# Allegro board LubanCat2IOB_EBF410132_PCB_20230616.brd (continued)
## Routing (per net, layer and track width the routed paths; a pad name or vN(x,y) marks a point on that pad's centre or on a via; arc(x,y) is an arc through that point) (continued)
UART4_RX_M1: length 79.3
  TOP w0.156: J4.17 v1(61.28,64.94)
  ART04 w0.142: v1(61.28,64.94) 61.28,32.76 v1(59,30.48)
  BOTTOM w0.156: v1(59,30.48) 58.52,30.96 58.52,32.07 58.83,32.38 60.43,32.38 60.8,32.01 60.8,27.72 60.41,27.33 59.61,27.33 55.68,23.39 54.08,23.39 53.47,24 51.79,24 51.38,24.41 40.61,24.41 40.28,24.08 40.28,21.44 40.13,21.28 39.01,21.28 38.61,20.88 38.61,17.78 37.62,16.79 U13.1
UART4_TX_M1: length 76.4
  TOP w0.156: J4.15 60.78,65.44 v1(60.28,65.94)
  ART04 w0.142: v1(60.28,65.94) 60.78,65.44 60.78,33.25 v1(59,31.48)
  BOTTOM w0.156: v1(59,31.48) 59.61,30.87 59.61,27.94 56.08,24.41 52.01,24.41 51.04,25.38 33.66,25.38 33.22,24.94 33.22,21.95 34.57,20.6 U13.4
UART7_RX: length 21.7
  TOP w0.156: R50.2 92.56,22.3 92.56,19.68 D9.1 91.82,16.89 91.57,16.63 87.64,16.63 87.33,16.32 87.33,8.25 J13.3
UART7_RX_M1: length 76.1
  TOP w0.156: R50.1 v1(91.82,24.78) ; J4.21 v1(62.28,64.94)
  ART03 w0.142: v1(91.82,24.78) 91.82,28.67 91.49,29 77.19,29 75.54,27.35 69.16,27.35 66.1,30.41 64.02,30.41 63.75,30.15 63.75,29.42 v1(64.28,28.89)
  ART04 w0.142: v1(64.28,28.89) 64.85,29.45 64.85,31.26 64.56,31.54 63.1,31.54 62.81,31.83 62.81,38.69 62.28,39.22 v1(62.28,64.94)
UART7_TX: length 17.6
  TOP w0.156: J13.4 86.99,10.45 86.99,16.63 87.3,16.94 89.91,16.94 90.22,17.25 D8.1 90.92,19.63 90.92,22.35 R49.2
UART7_TX_M1: length 73.3
  TOP w0.156: J4.19 61.78,65.44 v1(61.28,65.94) ; R49.1 v1(90.22,24.78)
  ART03 w0.142: v1(90.22,24.78) 90.2,24.8 90.2,28.41 89.91,28.7 77.44,28.7 75.72,26.97 69.01,26.97 66.09,29.89 v1(64.28,29.89)
  ART04 w0.142: v1(61.28,65.94) 61.8,65.43 61.8,39.02 62.41,38.41 62.41,30.18 62.69,29.89 v1(64.28,29.89)
UART9_RX: length 13
  TOP w0.156: R44.2 87.65,22.41 87.65,19.57 D7.1 87.02,17.99 86.71,17.67 85.18,17.67 84.87,17.36 84.87,13.73 J14.3
UART9_RX_M1: length 77.3
  TOP w0.156: J4.5 v1(58.28,64.94) ; R44.1 v1(87.02,24.78)
  ART03 w0.142: v1(55,30.48) 55.49,29.99 62.72,29.99 63.01,29.71 63.01,27.66 63.29,27.38 67.64,27.38 68.78,26.23 78.87,26.23 80.98,28.34 86.74,28.34 87.02,28.06 v1(87.02,24.78)
  ART04 w0.142: v1(58.28,64.94) 58.28,62.83 55.91,60.45 55.91,34.06 55,33.16 v1(55,30.48)
UART9_TX: length 10.7
  TOP w0.156: R43.2 89.25,22.41 89.25,19.57 D6.1 88.62,17.63 88.31,17.32 86.13,17.32 85.85,17.04 85.85,15.29
UART9_TX_M1: length 83.2
  TOP w0.156: R43.1 v1(88.62,24.78) ; J4.3 57.78,65.44 v1(57.28,65.94)
  ART03 w0.142: v1(88.62,24.78) 88.62,24.44 88.34,24.15 86.82,24.15 86.44,24.53 86.44,27.68 86.15,27.96 81.1,27.96 78.97,25.83 68.66,25.83 67.44,27.05 62.92,27.05 62.64,27.33 62.64,29.4 62.35,29.69 54.79,29.69 v1(54,30.48)
  ART04 w0.142: v1(54,30.48) 54.51,30.98 54.51,33.32 55.58,34.39 55.58,60.7 57.76,62.89 57.76,65.46 v1(57.28,65.94)
USB2_HOST2_DM: length 104.7
  TOP w0.158: v1(115.93,65.8) 115.63,65.51 99.17,65.51 98.48,64.82 88.7,64.82 87.17,63.29 87.17,58.14 86.41,57.38 75.56,57.38 75.21,57.73 75.21,58.12 75.28,58.19 J4.74 ; R152.2 v1(127.28,78.58)
  ART04 w0.144: v1(127.28,78.58) 126.94,78.25 126.94,77.54 126.48,77.07 122.24,77.07 121.57,76.4 102.21,76.4 101.65,75.84 101.65,63.6 101.88,63.37 111.71,63.37 113.84,65.5 115.62,65.5 v1(115.93,65.8)
USB2_HOST2_DP: length 105.9
  TOP w0.158: J4.72 74.78,58.19 74.85,58.12 74.85,57.58 75.41,57.02 86.56,57.02 87.53,57.99 87.53,63.14 88.85,64.46 98.63,64.46 99.32,65.15 115.62,65.15 v1(115.93,64.84) ; R153.2 v1(126.26,78.58)
  ART04 w0.144: v1(126.26,78.58) 126.6,78.25 126.6,77.68 126.33,77.42 122.1,77.42 121.43,76.75 102.07,76.75 101.3,75.98 101.3,63.45 101.74,63.02 111.85,63.02 113.98,65.15 115.62,65.15 v1(115.93,64.84)
USB2_HOST3_DM: length 74.1
  TOP w0.158: v1(89.13,62.86) 89.43,62.56 89.43,57.7 87.59,55.86 74.62,55.86 73.71,56.76 73.71,58.12 73.78,58.19 J4.68
  BOTTOM w0.158: v1(89.13,62.86) 89.43,62.56 89.43,62.02 89.79,61.66 96.39,61.66 98.75,64.02 98.75,94.12 99.09,94.46 99.47,94.46 arc(99.57,94.42) 99.62,94.31 arc(99.66,94.2) 99.77,94.15 100.1,94.15 arc(100.21,94.2) 100.25,94.31 arc(100.3,94.42) 100.41,94.46 100.73,94.46 arc(100.84,94.42) 100.89,94.31 arc(100.93,94.2) 101.04,94.15 101.36,94.15 arc(101.47,94.2) 101.52,94.31 arc(101.56,94.42) 101.67,94.46 104.78,94.46 104.85,94.39 U28.14
USB2_HOST3_DP: length 74
  TOP w0.158: v1(90.1,62.86) 89.79,62.56 89.79,57.56 87.73,55.5 74.47,55.5 73.35,56.61 73.35,58.12 73.28,58.19 J4.66
  BOTTOM w0.158: v1(90.1,62.86) 89.79,62.56 89.79,62.17 89.94,62.02 96.24,62.02 98.39,64.17 98.39,94.27 98.94,94.82 104.78,94.82 104.85,94.89 U28.15
USB3_HOST1_DM: length 157.6
  TOP w0.158: v1(115.73,37.04) 116,37.31 116,38.52 115.68,38.84 53.63,38.84 51.71,36.92 51.71,27.76 51.78,27.69 J1.80 ; R148.2 v1(121.06,78.58)
  ART04 w0.144: v1(121.06,78.58) 120.46,77.99 100.96,77.99 100.06,77.09 100.06,53.71 100.75,53.01 103.9,53.01 arc(103.97,52.99) 104,52.92 arc(104.02,52.86) 104.09,52.83 104.48,52.83 arc(104.54,52.86) 104.57,52.92 arc(104.6,52.99) 104.66,53.01 105.05,53.01 arc(105.12,52.99) 105.15,52.92 arc(105.17,52.86) 105.24,52.83 105.63,52.83 arc(105.69,52.86) 105.72,52.92 arc(105.75,52.99) 105.81,53.01 117.07,53.01 117.36,52.73 117.36,40.32 116.04,39 116.04,37.35 v1(115.73,37.04)
USB3_HOST1_DP: length 159
  TOP w0.158: v1(116.69,37.04) 116.36,37.37 116.36,38.67 115.83,39.2 53.48,39.2 51.35,37.07 51.35,27.76 51.28,27.69 J1.78 ; R149.2 v1(122.07,78.58)
  ART04 w0.144: v1(122.07,78.58) 122.05,78.56 121.71,78.56 121.25,78.11 121.07,78.11 120.61,77.64 101.1,77.64 100.41,76.95 100.41,53.85 100.9,53.36 117.21,53.36 117.7,52.87 117.7,40.18 116.38,38.86 116.38,37.35 v1(116.69,37.04)
USB3_HOST1_SSRXN: length 158.4
  TOP w0.158: R150.2 v1(123.09,78.58) ; v1(113.36,45.36) 113.06,45.06 113.06,43.85 112.69,43.48 50.53,43.48 46.71,39.67 46.71,27.76 46.78,27.69 J1.60
  ART04 w0.144: v1(113.36,45.36) 113.05,45.67 113.05,51.84 112.7,52.18 99.6,52.18 99.15,52.63 99.15,80.35 99.75,80.95 118.35,80.95 119.54,79.76 123.09,79.76 123.42,79.43 123.42,78.92 v1(123.09,78.58)
USB3_HOST1_SSRXP: length 159.6
  TOP w0.158: R151.2 v1(124.1,78.58) ; J1.58 46.28,27.69 46.35,27.76 46.35,39.82 50.38,43.85 112.54,43.85 112.69,44 112.69,45.06 v1(112.39,45.36)
  ART04 w0.144: v1(112.39,45.36) 112.7,45.67 112.7,51.69 112.56,51.84 99.46,51.84 98.81,52.49 98.81,80.5 99.61,81.3 118.49,81.3 119.68,80.11 123.24,80.11 123.77,79.57 123.77,78.92 v1(124.1,78.58)
USB3_HOST1_SSTXN: length 186.5
  TOP w0.158: J1.64 47.78,27.69 47.71,27.76 47.71,39.28 51.03,42.59 115.48,42.59 116.01,43.12 116.01,45.06 v1(116.31,45.36) ; C142.2 v1(128.3,78.58)
  ART04 w0.144: v1(116.31,45.36) 116,45.05 116,44.24 114.72,42.96 98.07,42.96 97.42,43.61 97.42,80.96 98.7,82.24 115.03,82.24 116.32,83.53 120.06,83.53 120.86,82.72 129.84,82.72 130.45,82.12 130.45,77.56 130.02,77.14 128.98,77.14 128.63,77.48 128.63,78.25 v1(128.3,78.58)
USB3_HOST1_SSTXP: length 186.5
  TOP w0.158: v1(115.34,45.36) 115.65,45.06 115.65,43.27 115.33,42.95 50.88,42.95 47.35,39.43 47.35,27.76 47.28,27.69 J1.62 ; C143.2 v1(129.31,78.58)
  ART04 w0.144: v1(129.31,78.58) 128.98,78.25 128.98,77.63 129.12,77.48 129.88,77.48 130.1,77.7 130.1,79.08 arc(130.04,79.23) 129.9,79.29 arc(129.75,79.35) 129.69,79.49 129.69,79.66 arc(129.75,79.8) 129.9,79.86 arc(130.04,79.92) 130.1,80.06 130.1,80.23 arc(130.04,80.38) 129.9,80.44 arc(129.75,80.5) 129.69,80.64 129.69,80.81 arc(129.75,80.95) 129.9,81.01 arc(130.04,81.07) 130.1,81.21 130.1,81.98 129.7,82.38 120.72,82.38 119.91,83.18 116.46,83.18 115.17,81.89 98.84,81.89 97.76,80.82 97.76,71.08 arc(97.8,70.99) 97.89,70.95 arc(97.98,70.91) 98.02,70.82 98.02,70.5 arc(97.98,70.41) 97.89,70.37 arc(97.8,70.34) 97.76,70.25 97.76,69.93 arc(97.8,69.84) 97.89,69.8 arc(97.98,69.76) 98.02,69.67 98.02,69.35 arc(97.98,69.26) 97.89,69.22 arc(97.8,69.19) 97.76,69.1 97.76,68.78 arc(97.8,68.69) 97.89,68.65 arc(97.98,68.61) 98.02,68.52 98.02,68.2 arc(97.98,68.11) 97.89,68.07 arc(97.8,68.04) 97.76,67.95 97.76,67.63 arc(97.8,67.54) 97.89,67.5 arc(97.98,67.46) 98.02,67.37 98.02,67.05 arc(97.98,66.96) 97.89,66.92 arc(97.8,66.89) 97.76,66.8 97.76,66.51 arc(97.81,66.41) 97.9,66.37 arc(98,66.33) 98.04,66.23 98.04,65.93 arc(98,65.84) 97.9,65.79 arc(97.81,65.75) 97.76,65.66 97.76,65.36 arc(97.81,65.26) 97.9,65.22 arc(98,65.18) 98.04,65.08 98.04,64.78 arc(98,64.69) 97.9,64.64 arc(97.81,64.6) 97.76,64.51 97.76,64.21 arc(97.81,64.11) 97.9,64.07 arc(98,64.03) 98.04,63.93 98.04,63.63 arc(98,63.54) 97.9,63.49 arc(97.81,63.45) 97.76,63.36 97.76,43.75 98.21,43.3 113.4,43.3 arc(113.51,43.35) 113.56,43.47 arc(113.61,43.59) 113.73,43.63 113.97,43.63 arc(114.09,43.59) 114.14,43.47 arc(114.18,43.35) 114.3,43.3 114.57,43.3 115.65,44.39 115.65,45.05 v1(115.34,45.36)
USB3_OTG0_DM: length 107.4
  TOP w0.158: v1(24.55,94.52) J36.B7 24.55,91.78 24.48,91.71 24.48,91.11 25.63,89.96 27.28,89.96 27.44,90.12 ; J36.A7 v1(23.55,94.52) ; v1(40.56,72.59) 40.26,72.89 40.26,80.39 39.45,81.2 30.94,81.2 30.33,81.81 30.33,89.4 29.78,89.95 27.6,89.95 27.44,90.11 27.44,90.12 ; 27.44,90.12 D26.1 ; v1(52.83,29.48) 53.13,29.17 57.84,29.17 58.21,28.8 58.21,27.76 58.28,27.69 J2.6
  BOTTOM w0.158: v1(23.55,94.52) v1(24.55,94.52) ; v1(52.83,29.48) 52.52,29.17 51.34,29.17 51.05,29.46 51.05,30.86 arc(51.11,31) 51.26,31.06 arc(51.4,31.12) 51.46,31.27 51.46,31.49 arc(51.4,31.64) 51.26,31.7 arc(51.11,31.76) 51.05,31.9 51.05,32.13 arc(51.11,32.27) 51.26,32.33 arc(51.4,32.39) 51.46,32.53 51.46,32.76 arc(51.4,32.9) 51.26,32.96 arc(51.11,33.02) 51.05,33.17 51.05,34.21 50.32,34.95 38.43,34.95 38.18,35.2 38.18,59.13 37.19,60.12 37.19,62.28 40.26,65.35 40.26,72.29 v1(40.56,72.59)
USB3_OTG0_DP: length 107.3
  TOP w0.158: 27.44,89.43 27.44,89.44 27.28,89.6 25.48,89.6 24.12,90.96 24.12,91.71 24.05,91.78 J36.A6 24.05,94.88 23.89,95.04 23.21,95.04 23.05,94.88 J36.B6 ; 27.44,89.43 D25.1 ; 27.44,89.43 27.6,89.59 29.63,89.59 29.97,89.25 29.97,81.66 30.79,80.84 39.3,80.84 39.9,80.24 39.9,72.89 v1(39.6,72.59) ; v1(52.83,28.51) 53.13,28.81 57.7,28.81 57.85,28.65 57.85,27.76 57.83,27.73 57.83,27.67 57.78,27.62 J2.4
  BOTTOM w0.158: v1(39.6,72.59) 39.9,72.29 39.9,65.5 36.83,62.43 36.83,59.97 37.82,58.98 37.82,35.05 38.28,34.59 50.17,34.59 50.69,34.06 50.69,29.31 51.19,28.81 52.52,28.81 v1(52.83,28.51)
USB3_OTG0_ID: length 163.2
  TOP w0.156: J2.10 59.28,28.39 v1(58.78,28.89)
  ART03 w0.142: v1(58.78,28.89) 59.5,28.18 59.5,26.74 58.17,25.41 58.17,19.72 57.64,19.19 36.81,19.19 36.53,19.47 36.53,34.16 33.63,37.05 8.53,37.05 8.24,37.34 8.24,72.81 7.06,73.99 7.06,86.89 7.49,87.32 20.07,87.32 21.32,88.58 23.85,88.58 24.13,88.86 24.13,92.27 24.33,92.48 28.69,92.48 v1(28.97,92.76)
  BOTTOM w0.156: R160.2 26.05,96.92 28.91,96.92 29.29,96.54 29.29,93.07 v1(28.97,92.76)
USB3_OTG0_VBUSDET: length 151.7
  TOP w0.156: R158.2 v1(23.61,89.12) ; v1(60.28,28.89) 59.78,28.39 J2.12
  ART03 w0.142: v1(23.61,89.12) 23.1,89.63 21.21,89.63 19.43,87.85 6.53,87.85 6.05,87.37 6.05,73.48 7.81,71.71 7.81,36.83 8.1,36.55 33.5,36.55 35.53,34.52 35.53,19.2 35.84,18.89 57.76,18.89 58.47,19.6 58.47,25.29 59.79,26.62 59.79,28.4 v1(60.28,28.89)
  BOTTOM w0.156: R158.2 v1(23.61,89.12)
USB20_DM1: length 9
  TOP w0.158: R152.1 127.31,80.39 U22.7 U22.4 127.31,83.18 126.55,83.95 126.55,84.58 126.76,84.79 127.17,84.79 127.35,84.97 127.35,86.26 127.18,86.43 126.7,86.43 126.54,86.59 126.54,87.02 126.7,87.18 J19.11
USB20_DP1: length 7.9
  TOP w0.158: R153.1 126.81,80.9 U22.6 U22.5 126.81,83.17 126.19,83.8 126.19,84.58 125.96,84.81 125.55,84.81 125.35,85.01 J19.12
USB20_HOST2_PWR_EN: length 181.1
  TOP w0.156: v1(45.05,10.26) 44.73,10.58 44.73,19.27 43.28,20.72 J1.45
  BOTTOM w0.156: R154.1 117.88,97.99 117.51,97.62 117.51,82.34 117.49,82.32 117.49,78.19 117.8,77.87 120.55,77.87 121.13,77.29 121.13,71.4 120.82,71.09 117.73,71.09 116.51,69.87 116.51,67.94 115.93,67.36 107.96,67.36 107.42,66.82 107.42,57.79 106.45,56.82 106.45,55.29 108.2,53.54 108.2,38.13 107.89,37.82 97.44,37.82 97.05,37.43 97.05,11.76 96.54,11.25 76.68,11.25 74.83,9.39 45.91,9.39 v1(45.05,10.26)
USB20_HUB_PWR_EN: length 107.6
  TOP w0.156: v1(120.02,81.03) 120.04,81.02 R170.1 ; v1(108.31,55.8) 107.83,56.28 96.62,56.28 93.93,53.59 47.6,53.59 47.28,53.9 J3.62
  BOTTOM w0.156: v1(120.02,81.03) 121.27,81.03 121.59,80.72 121.59,71 121.27,70.68 117.93,70.68 116.89,69.64 116.89,67.41 115.85,66.36 108.3,66.36 107.83,65.89 107.83,56.28 v1(108.31,55.8)
USB30_DM: length 25.8
  TOP w0.158: J19.2 126.74,90.38 126.58,90.54 126.58,91.3 126.01,91.87 122.35,91.87 120.44,89.96 117.73,89.96 116.97,89.2 116.97,84.32 117.58,83.71 121.41,83.71 121.62,83.5 121.62,83.16 121.56,83.09 U23.5 U23.6 121.56,80.85 R148.1
USB30_DP: length 24.5
  TOP w0.158: R149.1 122.05,80.37 U23.7 U23.4 122.05,83.09 121.99,83.16 121.99,83.65 121.56,84.07 117.73,84.07 117.33,84.47 117.33,89.05 117.88,89.6 120.59,89.6 122.5,91.51 125.86,91.51 126.22,91.15 126.22,90.55 126.05,90.38 J19.3
USB30_HOST1_PWR_EN: length 188.7
  TOP w0.156: J1.47 43.78,20.78 45.14,19.43 45.14,11.15 45.16,11.15 v1(46.05,10.26)
  BOTTOM w0.156: v1(46.05,10.26) 46.48,9.83 74.32,9.83 76.17,11.68 94.79,11.68 95.35,12.24 95.35,23.39 96.41,24.44 96.41,37.83 96.95,38.38 107.56,38.38 107.87,38.69 107.87,53.34 106.12,55.09 106.12,57.15 106.96,57.98 106.96,67.2 107.59,67.84 115.6,67.84 116.15,68.4 116.15,70.23 117.45,71.52 120.34,71.52 120.65,71.84 120.65,76.98 120.34,77.29 116.8,77.29 116.49,77.6 116.49,83.93 117.14,84.58 117.14,97.71 118.54,99.11 126.85,99.11 R156.1
USB30_RXN: length 11.4
  TOP w0.158: J19.5 121.72,88.88 121.56,88.72 121.56,88.36 121.82,88.11 123.26,88.11 123.9,87.48 123.9,86.99 123.13,86.22 123.13,83.16 123.06,83.09 U23.2 U23.9 123.06,80.39 R150.1
USB30_RXP: length 10.1
  TOP w0.158: R151.1 123.55,80.9 U23.10 U23.1 123.55,83.09 123.49,83.15 123.49,86.07 124.26,86.84 124.26,87.63 123.53,88.36 123.53,88.72 123.69,88.88 J19.6
USB30_TXN: length 10.2
  TOP w0.158: J19.8 129.05,88.88 129.21,88.72 129.21,88.37 128.54,87.7 128.54,86.59 129.13,86 129.13,84.65 128.38,83.91 128.38,83.16 128.31,83.09 U22.2 U22.9 128.31,80.37 C142.1
USB30_TXP: length 10.3
  TOP w0.158: C143.1 128.81,80.85 U22.10 U22.1 128.81,83.09 128.74,83.16 128.74,83.76 129.49,84.5 129.49,86.15 128.91,86.74 128.91,87.55 129.57,88.22 129.57,88.7 129.75,88.88 J19.9
USB_HUB_DM1: length 10.3
  BOTTOM w0.158: U28.11 106.95,92.46 106.43,91.95 U30.2 U30.9 106.43,90.31 106.36,90.24 106.36,89.93 105.55,89.11 105.55,87.64 105.79,87.4 107.33,87.4 107.78,86.95 107.78,86.32 J20.2
USB_HUB_DM2: length 4.9
  BOTTOM w0.158: J20.8 107.86,89.24 107.86,89.25 107.86,90.24 107.93,90.31 U30.6 U30.5 107.95,91.64 U28.9
USB_HUB_DM3: length 32.7
  TOP w0.158: v1(111.56,73.37) 111.27,73.66 111.27,74.18 110.85,74.6 104.79,74.6 104.51,74.88 104.51,82.47 v1(104.76,82.72)
  BOTTOM w0.158: U28.7 108.95,92.29 108.88,92.23 108.88,91.27 110.02,90.13 110.02,84.36 109.65,83.99 104.98,83.99 104.5,83.51 104.5,82.98 v1(104.76,82.72) ; R64.2 v1(111.56,73.37)
USB_HUB_DP1: length 10.3
  BOTTOM w0.158: U28.12 106.45,92.52 105.93,92.01 U30.1 U30.10 105.93,90.31 106,90.24 106,90.08 105.19,89.26 105.19,87.49 105.64,87.04 107.18,87.04 107.42,86.8 107.42,86.32 J20.3
USB_HUB_DP2: length 4.9
  BOTTOM w0.158: J20.9 107.5,89.4 107.5,90.24 107.43,90.31 U30.7 U30.4 107.45,91.64 U28.10
USB_HUB_DP3: length 32.7
  TOP w0.158: v1(103.9,82.72) 104.14,82.47 104.14,74.73 104.64,74.23 110.7,74.23 110.91,74.03 110.91,73.66 v1(110.62,73.37)
  BOTTOM w0.158: U28.8 108.45,92.29 108.52,92.23 108.52,91.12 109.66,89.98 109.66,84.51 109.5,84.36 104.83,84.36 104.13,83.66 104.13,82.96 v1(103.9,82.72) ; R65.2 v1(110.62,73.37)
USB_OTG_VBUS: length 6.4
  TOP w0.156: R158.1 22.61,89.16 v1(22.56,89.1)
  TOP w0.305: J36.A9 21.25,91.88 21.41,91.72 21.55,91.85 J36.B4 ; J36.A4 26.35,91.85 26.21,91.72 26.05,91.88 J36.B9
  vias: v1(21.41,91.69) v1(21.41,90.8) v1(21.56,89.1) v1(21.56,88.1) v1(26.21,91.69) v1(26.21,90.8)
USB_OTG_VBUS_EN: length 114.8
  TOP w0.156: J1.43 v1(42.78,23.89)
  ART03 w0.142: v1(32.23,91.39) 32.74,90.88 32.74,77.14 29.72,74.11 22.43,74.11 21.39,73.07 14.4,73.07 13.56,72.23 13.56,48.62 14.48,47.7 14.48,42.75 14.76,42.46 34.72,42.46 43.17,34.02 43.17,24.27 v1(42.78,23.89)
  BOTTOM w0.156: R161.1 27.94,90.55 28.19,90.8 31.65,90.8 v1(32.23,91.39)
N28611: length 5.7
  TOP w0.254: C24.1 R11.1 R13.1 2.1,70.41 1.83,70.14 1.83,68.62 2.02,68.43 U5.4
N15580021: length 3.1
  TOP w0.156: U18.25 70.69,70.98 R91.2
N15580025: length 3.4
  TOP w0.156: R92.2 70.29,71.57 U18.24
N15580029: length 3.7
  TOP w0.156: U18.23 69.89,72.32 R93.2
N15580033: length 4
  TOP w0.156: R94.2 69.49,73.06 U18.22
N15580037: length 3.7
  TOP w0.156: U18.27 71.49,72.46 R95.2
N15580041: length 3.4
  TOP w0.156: R96.2 71.09,71.72 U18.26
N15582684: length 5.7
  TOP w0.156: U18.31 73.96,74.7 74.5,74.16 74.5,72.67 75.11,72.06 v1(75.17,72.06) R104.2
  BOTTOM w0.156: v1(75.17,72.06) 75.18,72.06 75.2,72.07 R103.2
N15584123: length 9
  TOP w0.156: Y3.3 80.28,77.58 80.14,77.72 76.02,77.72 75.85,77.55 75.85,77.54 ; 75.85,77.54 75.7,77.69 75.39,77.69 75.23,77.54 75.23,77.11 74.83,76.7 U18.36 ; 75.85,77.54 C77.1
N15584130: length 7.5
  TOP w0.156: U18.37 74.76,77.1 74.93,77.26 74.93,77.69 75.26,78.02 75.72,78.02 75.85,78.16 ; 75.85,78.16 C76.1 ; 75.85,78.16 75.86,78.16 76,78.02 78.54,78.02 78.78,78.27 Y3.1
N15584385: length 9
  TOP w0.156: U18.12 66.16,77.9 64.41,76.15 C78.1 R107.2 R184.2 64.41,74.05 64.41,73.56 64.28,73.43 63.47,73.43 63.32,73.28 D22.1
N15584944: length 3.8
  TOP w0.156: U18.32 74.04,75.1 74.88,74.27 74.88,73.48 75.29,73.07 R110.1
N15590489: length 3.8
  TOP w0.156: U18.39 74.02,77.9 74.24,78.12 74.82,78.12 75.06,78.36 75.06,79.45 75.29,79.68 R100.1
N15599533: length 3.1
  TOP w0.156: R118.2 89.87,70.98 U19.25
N15599537: length 3.4
  TOP w0.156: R119.2 89.47,71.57 U19.24
N15599541: length 3.7
  TOP w0.156: U19.23 89.07,72.32 R120.2
N15599545: length 4
  TOP w0.156: R122.2 88.67,73.06 U19.22
N15599549: length 3.7
  TOP w0.156: U19.27 90.67,72.46 R123.2
N15599553: length 3.4
  TOP w0.156: R124.2 90.27,71.72 U19.26
N15600826: length 5.8
  TOP w0.156: U19.31 93.14,74.7 93.68,74.16 93.68,72.67 v1(94.28,72.06) R132.2
  BOTTOM w0.156: v1(94.28,72.06) 94.3,72.07 R130.2
N15601838: length 7.5
  TOP w0.156: U19.37 93.94,77.1 94.1,77.26 94.1,77.69 94.44,78.02 94.89,78.02 95.03,78.16 ; Y4.1 97.95,78.34 97.64,78.02 95.17,78.02 95.04,78.16 95.03,78.16 ; C98.1 95.03,78.16
N15601846: length 8.9
  TOP w0.156: 95.03,77.54 94.87,77.69 94.57,77.69 94.41,77.54 94.41,77.11 94,76.7 U19.36 ; 95.03,77.54 C99.1 ; 95.03,77.54 95.03,77.55 95.2,77.72 99.24,77.72 99.45,77.5 Y4.3
N15602147: length 9.2
  TOP w0.156: D35.1 82.22,73.35 82.35,73.48 83.43,73.48 83.56,73.61 R238.2 R136.2 C101.1 83.56,76.16 85.3,77.9 U19.12
N15602572: length 3.8
  TOP w0.156: R139.1 94.46,73.07 94.03,73.5 94.03,74.32 93.25,75.1 U19.32
N15603170: length 3.6
  BOTTOM w0.508: C100.1 93.64,79.93 J18.1
N15605512: length 3.8
  TOP w0.156: U19.39 93.2,77.9 93.42,78.12 94,78.12 94.23,78.36 94.23,79.45 94.46,79.68 R121.1
N15772454: length 3
  TOP w0.156: R208.2 150.17,48.36 150.33,48.19 J26.14
N15774097: length 3.9
  TOP w0.156: J23.14 150.68,70.93 150.6,70.84 149.99,70.84 149.77,71.06 149.77,71.77 149.48,72.06 R204.2
N16795890: length 3.6
  TOP w0.254: U5.5 v1(1.81,67.48)
  BOTTOM w0.254: v1(1.81,67.48) R225.1 R12.1
N17344359: length 10.5
  BOTTOM w0.762: J39.5 16.61,98.76 L2.1 8.49,98.76 J39.1
N17345183: length 6.3
  TOP w0.254: U2.4 1.79,40.49 1.54,40.74 1.54,42.2 1.82,42.47 R7.1 R6.1 C14.1
N17367006: length 5.8
  TOP w0.254: U1.4 2.02,54.46 1.75,54.73 1.75,56.11 2.09,56.45 2.92,56.45 R3.1 R1.1 C2.1
N17371141: length 1.9
  TOP w0.156: LED1.1 v1(137.65,98.39)
  BOTTOM w0.156: R4.2 137.61,98.34 v1(137.65,98.39)
N17385739: length 1.9
  TOP w0.156: LED2.1 v1(142.32,98.39)
  BOTTOM w0.156: v1(142.32,98.39) 142.27,98.34 R31.2
N17407470: length 3.2
  BOTTOM w0.156: J41.1 R51.2
N17407472: length 3.2
  BOTTOM w0.156: J41.7 140.2,26.82 R57.2
N17407474: length 3.4
  BOTTOM w0.156: J41.5 140.58,24.62 R54.2
N17407476: length 3.2
  BOTTOM w0.156: J41.3 R53.2
N17407478: length 3.2
  BOTTOM w0.156: J41.2 R52.2
N17407480: length 3.2
  BOTTOM w0.156: J41.8 R60.2
N17407510: length 3.2
  BOTTOM w0.156: J41.9 R61.2
N17408573: length 4.2
  BOTTOM w0.381: J11.1 75.38,81.15 75.98,80.56 C31.1
N17409833: length 5.2
  BOTTOM w0.156: U7.5 126.95,56.94 126.64,57.25 126.64,58.8 126.34,59.1 R17.1 R16.2
N17409879: length 4.4
  BOTTOM w0.254: U7.4 125.78,55.99 R15.1 R14.2 C32.2
N17410340: length 10
  BOTTOM w0.156: U14.2 139.87,42.85 139.7,42.68 U15.5 139.7,40.48 139.53,40.31 138.69,40.31 138.38,39.99 138.38,38.87 C52.1 R19.2
N17410342: length 10.5
  BOTTOM w0.156: R20.2 C51.1 138.43,40.81 138.62,41.01 U15.4 139.2,45.14 139.45,45.39 U14.3
N17410344: length 12.9
  BOTTOM w0.156: R21.2 R18.2 C47.1 140.2,38.27 U15.1 144.02,39.66 144.2,39.83 144.2,43.95 144.02,44.12 U14.7
N17411312: length 6.8
  TOP w0.173: J35.1 128.7,74.03 v1(128.24,73.57)
  BOTTOM w0.156: R22.2 128.03,71.54 128.24,71.75 v1(128.24,73.57)
  BOTTOM w0.173: R29.2 v1(128.24,73.57)
N17411326: length 4.2
  TOP w0.156: v1(125.48,73.57) 126.3,74.4 J35.7
  BOTTOM w0.156: R30.2 v1(125.48,73.57)
N17411361: length 2.7
  TOP w0.156: R62.1 117.9,65.78 J35.20
N17411393: length 2.7
  TOP w0.156: J35.22 117.1,65.83 R63.1
N17411481: length 3.4
  TOP w0.158: J35.38 110.7,69.55 110.92,69.77 110.92,70.41 v1(110.72,70.61)
  BOTTOM w0.158: v1(110.72,70.61) 110.62,70.71 R65.1
N17411507: length 3.4
  TOP w0.158: J35.36 111.5,69.55 111.28,69.77 111.28,70.31 v1(111.58,70.61)
  BOTTOM w0.158: v1(111.58,70.61) 111.56,70.64 R64.1
N17438974: length 1
  BOTTOM w0.254: R37.2 D4.2
N17440531: length 1
  BOTTOM w0.254: R67.2 D5.2
N17441588: length 4.2
  TOP w0.156: v1(70.74,20.42) 70.96,20.42 C49.1
  BOTTOM w0.156: U11.3 70.57,22.42 70.57,20.72 70.74,20.54 v1(70.74,20.42)
N17441590: length 5.5
  TOP w0.156: C49.2 70.01,20.37 68.66,20.37 68.03,21 v1(68.03,21)
  BOTTOM w0.156: v1(68.03,21) 68.03,22.42 U11.1
N17441592: length 6.2
  TOP w0.156: C50.1 76.32,20.25 76.05,20.52 73.59,20.52 v1(73.11,21)
  BOTTOM w0.156: U11.5 73.11,22.42 v1(73.11,21)
N17441594: length 6.3
  TOP w0.156: v1(71.83,21) 72.62,20.21 75.16,20.21 75.32,20.05 C50.2
  BOTTOM w0.156: v1(71.83,21) 71.83,22.42 U11.4
N17441596: length 6.2
  TOP w0.156: v1(74.37,21) 77.11,21 77.33,20.79 C48.1
  BOTTOM w0.156: U11.6 74.37,22.42 v1(74.37,21)
N17441598: length 6.3
  TOP w0.156: C45.1 72.59,19.8 72.22,19.8 71.02,21 v1(69.29,21)
  BOTTOM w0.156: v1(69.29,21) 69.29,22.42 U11.2
N17485809: length 3.4
  TOP w0.156: U20.5 v1(139.34,60.88)
  BOTTOM w0.156: v1(139.34,60.88) R75.1 R76.1
N17485876: length 5.7
  TOP w0.254: R73.1 C69.1 R74.1 139.41,58.59 139.6,58.77 139.6,59.68 139.34,59.93 U20.4
N17487342: length 6.2
  TOP w0.173: J17.38 145.9,85.82 145.59,86.13 v1(142.88,86.13)
  BOTTOM w0.173: R81.1 142.7,86.91 142.88,86.74 v1(142.88,86.13)
N17487441: length 2.5
  TOP w0.173: J17.10 138.9,86.11 v1(138.94,86.15)
  BOTTOM w0.173: R80.1 138.68,85.9 v1(138.94,86.15)
N17494240: length 33.4
  TOP w0.508: L19.1 132.93,86.69 J19.21
  ART04 w0.508: J19.21 132.92,84.65 132.54,84.27 120.22,84.27 119.78,84.72 J19.20
  BOTTOM w0.508: J19.22 J19.21 ; J19.20 J19.19
N17495021: length 2.5
  BOTTOM w0.156: U26.4 127.49,96.54 C147.1 R156.2
N17495041: length 2.1
  BOTTOM w0.156: R157.1 130.19,96.33 130.4,96.54 U26.3
N17495139: length 2.5
  BOTTOM w0.156: U24.4 120.69,96.54 C146.1 R154.2
N17495165: length 3.4
  BOTTOM w0.156: U24.3 124.84,96.54 125.04,96.34 125.04,95.51 124.89,95.36 R155.1
N17495663: length 24.5
  ART03 w0.508: J36.C1 J36.C3 ; J36.C2 J36.C4
  ART04 w0.508: J36.C3 28.14,94.24 28.14,95.63 27.71,96.06 19.89,96.06 19.48,95.65 J36.C4
  BOTTOM w0.508: L20.1 19.48,90.89 J36.C4
N17495859: length 2.3
  BOTTOM w0.156: R160.1 25.23,95.89 D27.3
N17496265: length 3
  BOTTOM w0.254: R162.1 25.97,88.96 25.78,88.77 25.78,87.8 25.97,87.61 U25.3
N17496334: length 4.9
  BOTTOM w0.254: U25.4 30.21,87.61 30.51,87.91 30.51,88.67 30.22,88.96 C150.1 R161.2
N17505436: length 1.6
  BOTTOM w0.156: R163.1 104.01,93.89 U28.13
N17505526: length 1.6
  BOTTOM w0.156: U28.16 104.14,95.39 R164.1
N17505593: length 2.3
  BOTTOM w0.156: U28.18 104.9,96.39 104.7,96.59 104.7,96.89 R165.1
N17505596: length 5.9
  BOTTOM w0.156: U28.17 104.73,95.89 C153.1 103.47,96.09 101.03,96.09 R166.1
N17506485: length 2.6
  BOTTOM w0.156: R168.1 108.56,98.01 107.62,98.01 107.45,97.84 U28.21
N17506866: length 6.6
  BOTTOM w0.305: R169.2 113.43,99.18 111.66,99.18 111.13,98.66 C158.1 110.82,98.25 110.82,96.68 110.53,96.39 U28.1
N17515649: length 7.2
  BOTTOM w0.156: Y2.1 115.43,96.39 115.27,96.24 112.5,96.24 112.15,96.59 C138.1 111.77,96.21 111.3,96.21 110.48,95.39 U28.3
N17515683: length 5.7
  BOTTOM w0.156: U28.4 110.44,94.89 111.45,95.9 111.79,95.9 C137.1 112.49,95.91 113.72,95.91 113.93,95.7 Y2.3
N17516865: length 28.9
  ART03 w0.508: J20.11 J20.12
  BOTTOM w0.508: J20.11 J20.5 101.05,81.35 L21.1 ; J20.6 J20.12
N17517489: length 2.8
  TOP w0.173: U29.4 118.97,79.41 C163.1 R170.2
N17517506: length 2
  TOP w0.173: U29.3 113.63,79.41 113.44,79.22 R171.1
N17532429: length 15.8
  TOP w0.156: R55.2 115.77,22.41 115.77,19.57 D19.1 115.14,10.9 J15.1
N17532431: length 16.5
  TOP w0.156: J15.2 114.15,11.91 114.15,18.33 D13.1 114.2,19.6 114.2,22.38 R56.2
N17532433: length 16.2
  TOP w0.156: R58.2 112.67,22.31 112.67,19.67 D12.1 111.94,11.7 J15.3
N17532435: length 16.3
  TOP w0.156: R59.2 111,22.38 111,19.6 D11.1 109.98,18.58 109.98,11.74 J15.4
N17532437: length 16.4
  TOP w0.156: R71.2 109.39,22.39 109.39,19.59 D10.1 108,18.2 108,11.76 J15.5
N17536330: length 4.2
  TOP w0.381: U3.2 v1(148.14,98.47)
  BOTTOM w0.381: R66.1 C16.1 C15.1 148.21,98.4 v1(148.14,98.47)
N17536407: length 3.2
  TOP w0.156: U3.3 v1(146.87,98.47)
  BOTTOM w0.156: R34.2 R32.2 146.81,98.42 v1(146.87,98.47)
N17536851: length 21.7
  BOTTOM w0.156: R26.1 C65.1 13.06,22.53 13.06,20.21 D3.2 15.11,18.15 15.11,12.49 15.52,12.09 21.64,12.09 21.95,11.77 SW3.2
N17545096: length 3.4
  TOP w0.156: U33.4 C172.1 R174.2
N17545112: length 2
  TOP w0.156: U33.3 147.39,59.42 R175.1
N17546367: length 3.2
  BOTTOM w0.124: J24.8 150.59,72.98 150.5,72.89 148.8,72.89 R231.2
N17546373: length 3.4
  BOTTOM w0.124: J24.12 150.59,74.98 150.5,74.89 150.33,74.89 149.81,75.41 148.79,75.41 R233.2
N17546399: length 3.2
  BOTTOM w0.124: J24.7 150.59,72.48 150.5,72.57 148.8,72.57 R230.2
N17546411: length 3.4
  BOTTOM w0.124: J24.11 150.59,74.48 150.5,74.57 150.19,74.57 149.68,75.08 148.81,75.08 R232.2
N17548144: length 3.4
  TOP w0.156: U36.4 C176.1 R185.2
N17548162: length 2.1
  TOP w0.156: R186.1 147.26,70.72 U36.3
N17550903: length 2
  TOP w0.173: U37.3 146.72,16.11 146.91,16.3 R190.1
N17550993: length 3.7
  TOP w0.173: R189.1 C201.1 142.11,16.3 142.31,16.11 U37.4
N17558620: length 2.9
  TOP w0.156: U38.3 v1(101.11,24.09)
  BOTTOM w0.156: R192.1 99.32,24.09 v1(101.11,24.09)
N17558699: length 5.2
  TOP w0.156: U38.4 96.64,24.09 96.42,24.3 96.42,25.27 96.65,25.5 C204.1 R191.2
N17562506: length 9
  TOP w0.156: C189.1 U34.4 ; C189.1 C192.1 U35.4 ; C189.1 R195.2
N17562520: length 5.1
  TOP w0.156: R196.1 144.78,63.93 144.58,63.72 144.58,62.89 144.74,62.72 U34.3
N17562633: length 5.2
  TOP w0.156: R197.1 144.7,67.99 144.45,67.74 144.45,67.03 144.69,66.78 U35.3
N17563970: length 9.1
  TOP w0.156: C193.1 142.11,41.07 142.31,40.88 U39.4 ; C193.1 C200.1 U40.4 ; C193.1 R200.1
N17564290: length 2.9
  TOP w0.156: U39.3 146.57,40.88 146.74,41.04 146.74,41.88 146.94,42.08 R198.1
N17565184: length 2.4
  TOP w0.156: R199.1 144.48,45.72 144.48,45.13 144.67,44.94 U40.3
N17577061: length 4.7
  TOP w0.156: U41.5 117.47,21.5 117.65,21.33 119.46,21.33 119.63,21.16 R202.1 R209.1
N17577114: length 3.8
  TOP w0.254: R201.1 C206.1 R203.1 116.52,20.67 U41.4
N17577685: length 3.3
  TOP w0.173: Q14.3 135,10.98 R205.2 134.05,11.93 Q10.1
N17577722: length 3.4
  TOP w0.156: Q14.1 134.5,7.38 R207.1 v1(133.68,6.27)
  BOTTOM w0.156: R207.1 v1(133.68,6.27)
N17590789: length 26.9
  TOP w0.254: C215.2 23.44,87.1 v1(22.89,86.54)
  ART03 w0.254: v1(31.09,92.93) 31.09,88.01 30.4,87.32 27.23,87.32 26.45,86.54 v1(22.89,86.54)
  BOTTOM w0.254: J25.3 36.61,88.68 J25.4 34.71,92.55 32.97,94.28 31.49,94.28 D34.1 31.09,93.83 v1(31.09,92.93)
N17590802: length 32.1
  TOP w0.254: v1(21.29,86.56) 20.74,87.1 C214.2
  ART03 w0.254: v1(31.09,96.01) 30.1,95.02 30.1,88.87 29.59,88.36 26.49,88.36 25.68,87.55 22.28,87.55 v1(21.29,86.56)
  BOTTOM w0.203: J25.2 37.35,94.93 R211.2
  BOTTOM w0.254: J25.2 35.64,93.22 34.66,93.22 33.13,94.74 31.42,94.74 D33.1 31.09,95.11 v1(31.09,96.01)
N17590849: length 7.3
  BOTTOM w0.381: R210.2 39.74,84.64 39.4,84.98 J25.1
N17609931: length 2
  BOTTOM w0.156: R213.2 C216.1 R214.1
N17615054: length 5.8
  BOTTOM w0.203: R217.2 35.18,73.58 34.85,73.91 34.85,74.77 D31.1 34.87,75.41 34.87,77.72 J31.1
N17615057: length 5.8
  BOTTOM w0.203: R218.2 34.49,73.9 34.49,74.77 D32.1 34.5,75.45 34.5,77.85 J31.2
N17639389: length 7.6
  TOP w0.156: Y1.1 135.01,76.24 135.35,75.9 138.71,75.9 C132.1 139.49,76.57 U21.5
N17639396: length 2
  TOP w0.156: U21.10 139.44,73.32 R144.1
N17639427: length 7.5
  TOP w0.381: U21.15 148.7,75.92 v1(150.26,77.48)
  BOTTOM w0.305: v1(150.26,77.48) 149.97,77.77 C134.1 ; C135.1 C134.1 ; C134.1 R145.1
N17639486: length 3.7
  TOP w0.179: U21.20 146.44,79.17 146.31,79.04 145.91,79.04 145.73,79.22 145.73,80.64 R77.1
N17639523: length 4.3
  TOP w0.179: U21.19 146.44,78.52 146.31,78.66 145.75,78.66 145.35,79.06 145.35,80.64 R78.1
N17639615: length 6.5
  TOP w0.179: U21.18 146.44,77.87 146.31,77.74 145.56,77.74 144.39,78.9 arc(144.35,79.01) 144.39,79.13 arc(144.44,79.24) 144.39,79.35 144.11,79.63 arc(144,79.68) 143.89,79.63 arc(143.78,79.58) 143.66,79.63 143.45,79.85 143.45,80.64 R87.1
N17639617: length 6.8
  TOP w0.179: U21.17 146.44,77.22 146.31,77.36 145.4,77.36 143.07,79.69 143.07,80.64 R111.1
N17639713: length 3.1
  TOP w0.156: R221.1 C133.1 138.06,74.72 Y1.3
N17683065: length 3.1
  TOP w0.254: U1.5 v1(1.53,53.51)
  BOTTOM w0.254: R2.1 v1(1.53,53.51)
N17697748: length 2.2
  TOP w0.156: U21.6 140,75.92 R221.2
N17699685: length 9.8
  BOTTOM w0.381: J11.11 74.6,97.68 71.58,97.68 70.87,96.97 R28.1
N17699996: length 5.2
  BOTTOM w0.381: R27.1 68.71,95.5 68.21,96 J11.13
N17700387: length 9.4
  BOTTOM w0.381: J18.11 93.02,97.53 90.09,97.53 89.28,96.72 R133.1
N17700720: length 5.3
  BOTTOM w0.381: R131.1 87.05,95.55 86.6,96 J18.13
N17737040: length 3.2
  BOTTOM w0.124: J22.16 150.59,58.78 150.5,58.87 148.77,58.87 R226.2
N17737043: length 3.2
  BOTTOM w0.124: R227.2 148.77,59.19 150.5,59.19 150.59,59.28 J22.17
N17737126: length 10.1
  BOTTOM w0.124: J22.19 152.27,60.28 152.36,60.37 152.67,60.37 152.98,60.68 152.98,63.46 152.67,63.77 151.66,63.77 151.53,63.9 151.53,64.5 151.22,64.81 149.85,64.81 149.85,64.81 148.77,64.81 R228.2
N17737138: length 9
  BOTTOM w0.124: R229.2 148.77,64.48 149.98,64.48 149.99,64.49 151.08,64.49 151.21,64.36 151.21,63.76 151.52,63.45 152.53,63.45 152.65,63.32 152.65,60.82 152.53,60.69 152.36,60.69 152.27,60.78 J22.20
N17802924: length 6.1
  BOTTOM w0.305: Q3.1 30.42,80.26 R9.2 29.96,79.67 29.46,79.17 Q4.3
N17802940: length 2.4
  BOTTOM w0.156: Q4.1 30.42,73.02 R234.1 R10.2
N17802978: length 5.5
  BOTTOM w0.305: R5.2 26.24,80.9 D20.1 J6.1
N17803061: length 2.6
  BOTTOM w0.305: Q3.3 29.38,83.61 R5.1
N17804550: length 2.4
  TOP w0.254: U16.5 v1(3.94,74.92)
  BOTTOM w0.254: v1(3.94,74.92) R236.1
N17804616: length 3.7
  TOP w0.254: C140.1 R235.1 R237.1 2.99,74.27 U16.4
N17822498: length 15.7
  BOTTOM w1.016: J11.15 71.12,88.05 C166.1 68.83,88.3 R173.1 68.58,88.05 J11.16
N17836581: length 15.7
  BOTTOM w1.016: J18.16 86.92,88.05 R183.1 89.16,88.18 C167.1 89.53,88.05 J18.15

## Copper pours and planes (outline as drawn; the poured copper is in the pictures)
1V05_PHY0 on TOP: 75.87,71.17 76.89,71.17 77.04,71.01 77.04,67.94 73.89,67.94 73.89,68.53 75.62,68.53 75.87,68.78
1V05_PHY1 on TOP: 95.05,71.17 96.06,71.17 96.22,71.01 96.22,67.94 93.07,67.94 93.07,68.53 94.79,68.53 95.05,68.78
1V8_DVDD_PHY0 on TOP: 64.31,68.14 65.1,68.14 65.1,67.69 65.25,67.53 67.61,67.53 67.61,66.95 64.47,66.95 64.31,67.1
1V8_DVDD_PHY1 on TOP: 83.41,68.14 84.2,68.14 84.2,67.69 84.35,67.53 85.65,67.53 85.65,66.95 83.57,66.95 83.41,67.1
3V3_DVDD_PHY0 on TOP: 66.5,71.19 64.49,71.19 64.31,71.01 64.31,70.02 65.1,70.02 65.1,70.48 65.23,70.61 66.5,70.61
3V3_DVDD_PHY1 on TOP: 85.6,71.19 83.59,71.19 83.41,71.01 83.41,70.02 84.2,70.02 84.2,70.48 84.33,70.61 85.6,70.61
12V on TOP: 4.7,40.15 7.16,40.15 7.32,40.31 7.32,42.54 7.16,42.69 5.97,42.69 5.84,42.57 5.84,40.97 5.71,40.84 4.7,40.84
12V on TOP: 135.2,11.17 135.2,13.05 135.41,13.25 137.82,13.25 138.02,13.05 138.02,11.25 137.82,11.05 135.33,11.05
12V on TOP: 116.87,24.3 116.87,25.42 117.25,25.8 117.25,28.34 117.04,28.55 113.49,28.55 113.21,28.27 113.21,26.46 113.41,26.26 116,26.26 116.18,26.08 116.18,24.3
12V on TOP: 4.7,54.12 7.16,54.12 7.32,54.28 7.32,56.51 7.16,56.66 5.97,56.66 5.84,56.54 5.84,54.94 5.71,54.81 4.7,54.81
12V on TOP: 4.7,68.09 7.16,68.09 7.32,68.25 7.32,70.48 7.16,70.63 5.97,70.63 5.84,70.51 5.84,68.91 5.71,68.78 4.7,68.78
12V on TOP: 2.31,83.1 12.88,83.1 13.11,82.88 13.11,79.83 12.85,79.57 9.45,79.57 9.14,79.88 9.14,81.07 8.86,81.35 2.31,81.35
12V on TOP: 145.31,31.62 145.31,28.44 149.73,28.44 150.14,28.85 150.14,31.24 149.76,31.62
12V on TOP: 1.32,77.77 1.32,79.88 1.5,80.06 3.78,80.06 3.89,79.96 3.89,79.07 3.81,78.99 3.45,78.99 3.33,78.86 3.33,77.75 3.17,77.59 1.5,77.59
12V on BOTTOM: 4.14,40.15 7.14,40.15 7.37,40.38 7.37,46.96 7.65,47.24 11.05,47.24 11.35,47.54 11.35,70.25 10.97,70.63 6.71,70.63 6.32,71.01 6.32,74.01 6.05,74.29 3.58,74.29 3.4,74.47 3.4,79.19 3.91,79.7 3.91,80.16 4.11,80.36 9.04,80.36 9.25,80.16 9.25,79.68 9.42,79.5 12.83,79.5 13.13,79.8 13.13,82.34 12.9,82.57 1.68,82.57 1.35,82.24 1.35,72.41 1.65,72.11 3.84,72.11 4.14,71.8 4.14,68.2 4.22,68.12 7.9,68.12 8.2,67.81 8.2,57.53 7.75,57.07 4.14,57.07 4.14,54.23 7.72,54.23 8.2,53.74 8.2,50.44 7.7,49.93 4.7,49.93 4.14,49.37
12V on ART04: 4.5,43.13 13.67,43.13 14.5,42.29 14.5,17.29 15.16,16.63 21.23,16.63 21.84,16.02 21.84,12.24 22.86,11.22 112.12,11.22 112.85,11.96 112.85,28.27 113.21,28.62 143.61,28.62 144.93,29.94 148.77,29.94 149.05,29.66 149.05,14.88 148.31,14.14 141.48,14.14 140.61,13.28 140.61,7.41 139.75,6.55 10.26,6.55 9.59,7.22 9.56,39.03 8.89,39.7 4.37,39.7 4.06,40 4.06,42.69
12V_IN on TOP: 2.34,85.98 8.76,85.98 9.3,86.51 9.3,92.1 8.74,92.66 2.95,92.66 2.34,92.05
GND on TOP: 2,5.5 0.94,5.94 0.5,7 0.5,98 0.94,99.06 2,99.5 61.65,99.5 61.65,87.65 95.99,87.65 95.99,99.5 156,99.5 157.06,99.06 157.5,98 157.5,7 157.06,5.94 156,5.5 ; 259 cut-outs
GND on TOP: 4.71,66.87 9.26,66.87 9.65,66.49 9.65,62.09 6.89,62.09 6.89,63.88 6.65,64.11 5.85,64.11 5.62,64.34 5.62,65.99 5.41,66.19 4.72,66.19 4.71,66.2
GND on TOP: 4.52,77.77 4.52,79.8 4.78,80.06 6.78,80.06 6.99,79.85 6.99,78.74 6.81,78.56 5.36,78.56 5.23,78.43 5.23,77.77
GND on GND02: 156,99.5 157.06,99.06 157.5,98 157.5,7 157.06,5.94 156,5.5 2,5.5 0.94,5.94 0.5,7 0.5,98 0.94,99.06 2,99.5 ; 5 cut-outs
GND on ART04: 156,99.5 157.06,99.06 157.5,98 157.5,7 157.06,5.94 156,5.5 2,5.5 0.94,5.94 0.5,7 0.5,87.88 12.06,87.88 12.65,87.3 12.65,74.95 12.17,74.47 9.3,74.47 8.28,73.45 8.28,44.55 7.67,43.94 3.96,43.94 3.23,43.2 3.23,39.7 3.89,39.04 8.38,39.04 8.79,38.63 8.79,7.21 9.68,6.32 140.74,6.32 141.45,7.03 141.45,12.7 142.19,13.43 148.89,13.43 149.86,14.4 149.86,29.79 150.37,30.3 156.29,30.3 156.72,30.73 156.72,80.72 156.16,81.28 155.14,81.28 154.64,81.78 154.64,91.97 154.1,92.5 148.92,92.5 148.29,93.14 148.29,95.02 147.9,95.4 132.84,95.4 132.21,96.03 132.21,98.55 131.85,98.9 32.44,98.9 31.7,98.17 31.7,89 31.06,88.36 0.5,88.36 0.5,98 0.94,99.06 2,99.5 ; 4 cut-outs
GND on ART04: 83.08,70.61 91.03,70.61 91.69,69.95 91.69,65.86 92.2,65.35 95.15,65.35 95.81,64.69 95.81,40.74 96.27,40.28 114.73,40.28 115.11,39.9 115.11,36.65 114.68,36.22 87.6,36.22 85.83,34.44 85.83,20.62 84.84,19.63 80.57,19.63 79.65,20.54 79.65,25.24 78.28,26.62 78.28,58.21 78.94,58.87 81.61,58.87 82.45,59.71 82.45,69.97
GND on ART04: 0.5,83.84 0.5,89.99 5.92,89.99 5.92,83.84
GND on ART04: 48.49,62.73 54.2,62.73 55.02,61.92 55.02,35.05 53.85,33.88 53.85,31.92 52.98,31.06 46.96,31.06 46.3,30.4 46.3,19.88 45.85,19.43 43.26,19.43 42.82,19.86 42.82,24.71 42.01,25.52 38.35,25.52 37.95,25.93 37.95,51.46 38.56,52.07 47.17,52.07 47.8,52.7 47.8,62.05
VCC5V0_SYS on TOP: 2.82,60.52 5.92,60.52 6.86,61.46 21.43,61.44 22.33,61.44 22.63,61.13 22.63,41.83 23.29,41.17 32.97,41.17 33.4,40.74 33.4,21.46 32.13,21.46 31.93,21.66 31.93,24.86 31.67,25.12 30.84,25.12 30.56,25.4 30.56,28.62 30.2,28.98 28.37,28.98 28.07,29.28 28.07,35.51 27.36,36.22 20.14,36.22 18.87,37.49 18.87,58.21 18.41,58.67 3.02,58.67 2.79,58.9 2.79,60.5
VCC5V0_USB on TOP: 11.91,76.02 11.99,75.84 12.17,75.76 15.16,75.76 15.34,75.84 15.42,76.02 15.42,78 15.34,78.18 15.16,78.25 12.17,78.25 11.99,78.18 11.91,78
VCC5V0_USB on TOP: 116.64,81.02 116.64,82.67 116.84,82.88 119.2,82.88 119.43,82.65 119.43,82.06 119.23,81.86 117.98,81.86 117.81,81.68 117.81,81.02
VCC5V0_USB on BOTTOM: 128.17,97.48 128.24,97.3 128.42,97.23 129.84,97.23 130.02,97.3 130.1,97.48 130.1,98.5 130.02,98.68 129.84,98.75 128.42,98.75 128.24,98.68 128.17,98.5
VCC5V0_USB on BOTTOM: 28.6,86 30.66,86 30.86,86.2 30.86,86.79 30.99,86.91 32.23,86.91 32.36,86.79 32.36,85.54 32.23,85.42 28.6,85.42
VCC5V0_USB on BOTTOM: 11.35,77.77 15.11,77.77 15.32,77.57 15.32,76.12 15.19,75.99 11.99,75.99 11.86,75.87 11.86,74.95 11.25,74.95 11.25,77.67
VCC5V0_USB on BOTTOM: 120.98,97.48 121.05,97.3 121.23,97.23 122.63,97.23 122.81,97.3 122.89,97.48 122.89,98.5 122.81,98.68 122.63,98.75 121.23,98.75 121.05,98.68 120.98,98.5
VCC5V0_USB on ART03: 116.66,82.11 119.2,82.11 119.46,82.37 119.46,82.8 119.25,83 117.73,83 117.53,83.21 117.53,96.36 117.75,96.59 130.12,96.59 130.45,96.92 130.45,98.5 130.18,98.78 116.87,98.78 116.33,98.24 116.33,82.44
VCC5V0_USB on ART04: 13.82,74.49 19.38,74.49 19.99,75.1 19.99,82.11 21.06,83.18 39.32,83.18 40.23,84.1 40.23,91.84 40.77,92.38 130.66,92.38 131.32,93.04 131.32,97.86 130.61,98.57 33.63,98.57 32.74,97.68 32.74,88.31 32.08,87.65 13.77,87.65 13.23,87.12 13.23,75.08
VDD_3V3 on TOP: 142.37,64.69 142.44,64.51 142.62,64.44 144.15,64.44 144.32,64.51 144.4,64.69 144.4,65.96 144.32,66.14 144.15,66.21 142.62,66.21 142.44,66.14 142.37,65.96
VDD_3V3 on TOP: 142.32,12.24 142.39,12.06 142.57,11.98 143.71,11.98 143.89,12.06 143.97,12.24 143.97,14.5 143.89,14.68 143.71,14.75 142.57,14.75 142.39,14.68 142.32,14.5
VDD_3V3 on TOP: 145.85,41.5 142.77,41.5 142.54,41.73 142.54,43.35 143.76,43.35 143.76,42.46 143.94,42.29 145.85,42.29 145.97,42.16 145.97,41.63
VDD_3V3 on TOP: 2.77,32.61 5.99,32.61 7.01,33.63 11.33,33.63 11.58,33.37 11.58,31.21 11.33,30.96 3.1,30.96 2.77,31.29
VDD_3V3 on TOP: 96.01,23.29 96.77,23.29 96.93,23.14 96.93,22.68 97.13,22.48 98.15,22.48 98.15,21.89 96.09,21.89 95.86,22.12 95.86,23.14
VDD_3V3 on BOTTOM: 20.93,82.06 18.64,82.06 18.54,82.17 18.54,84.48 18.64,84.58 19.51,84.58 19.66,84.43 19.66,83.08 19.79,82.95 20.93,82.95
VDD_3V3 on PWR05: 156,99.5 157.06,99.06 157.5,98 157.5,7 157.06,5.94 156,5.5 2,5.5 0.94,5.94 0.5,7 0.5,98 0.94,99.06 2,99.5 ; 5 cut-outs
VDD_3V3_EDP_TP on TOP: 99.19,22.48 100.66,22.48 100.66,21.89 100.15,21.89 99.87,21.61 99.87,20.8 100.13,20.54 103.2,20.54 103.66,21 106.15,21 106.22,20.93 106.22,19.33 99.01,19.33 99.01,22.3
VDD_3V3_EDP_TP on BOTTOM: 103.84,20.6 103.91,20.42 104.09,20.34 105.18,20.34 105.36,20.42 105.44,20.6 105.44,20.7 105.36,20.88 105.18,20.95 104.09,20.95 103.91,20.88 103.84,20.7
VDD_5V on TOP: 143.74,38.63 143.74,39.29 142.57,39.29 142.57,37.11 142.72,36.95 144.81,36.95 144.96,37.11 144.96,38.35 144.83,38.48 143.89,38.48
VDD_5V on TOP: 142.37,60.63 142.44,60.45 142.62,60.37 144.15,60.37 144.32,60.45 144.4,60.63 144.4,61.9 144.32,62.08 144.15,62.15 142.62,62.15 142.44,62.08 142.37,61.9
VDD_5V on TOP: 2.77,45.18 13.82,45.18 14.27,44.73 14.27,16.96 14.96,16.28 14.96,14.91 15.21,14.65 16.81,14.65 17.04,14.88 17.04,16.68 16.26,17.47 16.26,47.14 15.82,47.57 6.86,47.57 6.86,46.76 6.68,46.58 2.77,46.58
VDD_5V on TOP: 142.37,68.63 142.44,68.45 142.62,68.37 144.15,68.37 144.32,68.45 144.4,68.63 144.4,69.9 144.32,70.08 144.15,70.15 142.62,70.15 142.44,70.08 142.37,69.9
VDD_5V on TOP: 142.37,57.32 142.44,57.14 142.62,57.07 144.15,57.07 144.32,57.14 144.4,57.32 144.4,58.59 144.32,58.77 144.15,58.85 142.62,58.85 142.44,58.77 142.37,58.59
VDD_5V on TOP: 136.53,60.3 133.02,60.3 132.87,60.14 132.87,58.49 133.02,58.34 135.36,58.34 135.51,58.49 135.51,59.43 135.66,59.58 136.53,59.58
VDD_5V on BOTTOM: 136.88,58.21 134.82,58.21 134.65,58.04 134.65,57.35 133.83,57.35 133.83,58.04 133.65,58.21 132.54,58.21 132.26,57.93 132.26,55.62 130.02,55.62 130.02,56.33 131.57,56.33 131.65,56.41 131.65,59.64 131.9,59.89 136.19,59.89 136.47,60.17 137.08,60.17 137.08,58.42
VDD_5V on BOTTOM: 52.02,97.91 49.17,97.91 48.84,97.58 48.84,92.22 48.59,91.97 46.96,91.97 46.69,91.69 46.69,90.6 46.96,90.32 49.94,90.32 50.34,90.72 50.34,96.29 50.6,96.54 52.02,96.54
VDD_5V on BOTTOM: 28.04,79.68 28.04,81.78 28.24,81.99 29.46,81.99 29.67,81.78 29.67,80.64 29.26,80.23 29.26,79.5 28.22,79.5
VDD_5V on ART04: 9.53,43.94 14,43.94 15.24,42.69 15.24,17.88 15.67,17.45 21.82,17.45 22.61,16.66 22.61,12.59 23.19,12.01 111.15,12.01 111.89,12.75 111.89,28.44 113.08,29.64 132.33,29.64 132.82,30.12 132.82,31.39 133.22,31.8 144.93,31.8 145.29,32.15 145.29,39.16 144.98,39.47 135.51,39.47 135.08,39.04 135.08,36.14 134.72,35.78 125.48,35.78 124.92,36.34 124.92,53.41 125.48,53.97 143.99,53.97 144.63,54.61 144.63,70.02 144.2,70.46 142.32,70.46 141.83,69.97 141.83,68.07 141.12,67.36 138.35,67.36 137.87,66.87 137.87,56.69 137.54,56.36 134.11,56.36 133.73,56.74 133.73,57.88 134.19,58.34 135.31,58.34 135.51,58.54 135.51,59.97 135.08,60.4 120.65,60.4 119.94,59.69 119.94,36.09 119.13,35.28 87.96,35.28 86.92,34.24 86.92,18.94 86.39,18.41 36.65,18.41 35.79,19.27 35.79,41.5 35.13,42.16 30.78,42.16 30.18,42.77 30.18,76.48 30.73,77.03 50.14,77.03 50.98,77.87 50.98,91.03 50.47,91.54 41.78,91.54 41.17,90.93 41.17,83.03 40.51,82.37 21.49,82.37 20.68,81.56 20.68,74.49 19.95,73.77 9.59,73.77 8.89,73.07 8.89,44.57
VDD_CAM0_5V on TOP: 147.17,57.4 147.24,57.22 147.42,57.15 150.32,57.15 150.5,57.22 150.57,57.4 150.57,57.73 150.5,57.91 150.32,57.98 147.42,57.98 147.24,57.91 147.17,57.73
VDD_CAM0_5V on BOTTOM: 148.06,51.35 148.06,55.22 149,56.16 149,57.63 149.15,57.78 150.37,57.78 150.52,57.63 150.52,55.32 150.04,54.83 150.04,51.35 149.81,51.13 148.29,51.13
VDD_CAM1_5V on TOP: 147.19,68.88 147.27,68.7 147.45,68.63 150.37,68.63 150.55,68.7 150.62,68.88 150.62,69.13 150.55,69.31 150.37,69.39 147.45,69.39 147.27,69.31 147.19,69.13
VDD_CAM1_5V on BOTTOM: 148.16,69.82 150.57,69.82 150.77,70.02 150.77,70.63 152.1,70.63 152.1,69.24 151.64,68.78 148.29,68.78 148.16,68.91
VDD_LCD0_5V on TOP: 150.88,65.58 150.88,63.8 151.13,63.55 151.89,63.55 152.15,63.8 152.15,65.58
VDD_LCD1_3V3 on TOP: 145.06,43.35 147.09,43.35 147.27,43.53 147.27,44.42 150.37,44.42 150.5,44.29 150.5,43.96 150.62,43.84 152.12,43.84 152.12,43.05 149.91,43.05 149.78,43.18 149.78,43.71 149.66,43.84 147.98,43.84 147.88,43.73 147.88,42.82 147.8,42.74 145.06,42.74
VDD_LCD1_5V on TOP: 150.83,42.85 150.83,40.43 150.7,40.31 150.7,39.92 150.83,39.8 151.87,39.8 152.12,40.05 152.12,42.85
(no net) on BOTTOM: 2,5.5 0.94,5.94 0.5,7 0.5,98 0.94,99.06 2,99.5 101.02,99.5 101.02,97.79 101.45,97.79 101.45,97.25 103.63,97.25 103.63,98.14 101.88,98.14 101.88,99.5 103.66,99.5 103.66,98.9 104.44,98.9 104.44,99.5 108.92,99.5 108.92,98.83 110.49,98.83 110.49,98.29 111.02,98.29 111.02,98.83 111.48,98.83 111.48,99.5 113.72,99.5 113.72,98.37 115.85,98.37 115.85,98.19 115.37,98.19 115.37,98.01 113.28,98.01 113.28,94.05 116.08,94.05 116.08,98.01 116.05,98.01 116.05,98.37 116.28,98.37 116.28,99.5 156,99.5 157.06,99.06 157.5,98 157.5,7 157.06,5.94 156,5.5 ; 235 cut-outs
(no net) on ART03: 156,99.5 157.06,99.06 157.5,98 157.5,7 157.06,5.94 156,5.5 2,5.5 0.94,5.94 0.5,7 0.5,98 0.94,99.06 2,99.5 ; 167 cut-outs
CAN1_H on BOTTOM (solid shape): 37.24,13.56 36.31,12.9 35.73,13.48 35.71,13.56 35.73,13.63 36.31,14.21
DGB_TX on BOTTOM (solid shape): 2.27,20.25 2.32,20.27 2.37,20.25 3.06,19.55 2.32,18.78 1.57,19.55
HDMI_5V on BOTTOM: 55.55,97 59.23,97 59.39,96.85 59.39,96.36 59.23,96.21 54.41,96.21 54.25,96.36 54.25,97.91 55.42,97.91 55.42,97.13
HDMI_5V on ART03: 57.12,96.72 59.26,96.72 59.56,96.41 59.56,95.91 59.28,95.63 58.04,95.63 57.81,95.4 57.81,82.01 57.63,81.83 57,81.83 56.85,81.99 56.85,96.44
HP_SNS on TOP (solid shape): 36.22,96.96 36.3,96.78 36.22,96.6 35.63,96.01 34.64,96.78 35.63,97.56
HP_SNS on TOP (solid shape): 43.86,96.8 42.88,96.02 42.27,96.6 42.19,96.78 42.27,96.96 42.88,97.57
HP_SNS on TOP (solid shape): 45.32,96.98 45.39,96.8 45.32,96.62 44.72,96.03 43.74,96.8 44.72,97.57
M2PCIE_3V3 on TOP: 139.24,83.26 139.24,87.27 139.42,87.45 140.13,87.45 140.31,87.27 140.31,85.95 141.05,85.21 141.05,83.31 140.77,83.03 139.47,83.03
M2PCIE_3V3 on TOP: 136.02,67.81 136.02,70.02 136.19,70.2 137.54,70.2 137.69,70.35 137.69,71.32 139.04,71.32 139.22,71.14 139.22,68.02 139.01,67.81
M2PCIE_3V3 on TOP: 152.1,87.42 154.53,87.42 154.79,87.17 154.79,85.59 155.04,85.34 155.04,83.82 153.75,83.82 153.75,85.31 153.57,85.49 152.1,85.49 151.87,85.72 151.87,87.19
M2PCIE_3V3 on BOTTOM: 151.76,85.77 151.84,85.59 152.02,85.52 152.27,85.52 152.45,85.59 152.53,85.77 152.53,87.93 152.45,88.11 152.27,88.18 152.02,88.18 151.84,88.11 151.76,87.93
M2PCIE_3V3 on BOTTOM: 153.82,86.1 153.9,85.92 154.08,85.85 154.31,85.85 154.48,85.92 154.56,86.1 154.56,88.03 154.48,88.21 154.31,88.29 154.08,88.29 153.9,88.21 153.82,88.03
M2PCIE_3V3 on BOTTOM: 136.35,68.68 136.42,68.5 136.6,68.42 138.79,68.42 138.97,68.5 139.04,68.68 139.04,69.74 138.97,69.92 138.79,70 136.6,70 136.42,69.92 136.35,69.74
M2PCIE_3V3 on BOTTOM: 139.14,77.85 141.33,77.85 141.6,78.13 141.6,83.97 141.73,84.1 142.01,84.1 142.01,84.68 138.4,84.68 138.4,84.17 138.25,84.02 136.6,84.02 136.42,83.84 136.42,82.34 136.55,82.22 140.21,82.22 140.51,81.91 140.51,81.02 140.36,80.87 139.32,80.87 139.14,80.69
M2PCIE_3V3 on ART04: 136.12,83.71 136.12,68.35 136.58,67.89 140.69,67.89 141.2,68.4 141.2,76.93 141.91,77.64 143.54,77.64 143.97,78.08 143.97,79.65 143.54,80.08 141.4,80.08 140.97,80.51 140.97,83.69 140.56,84.1 136.5,84.1
MIC1_INN on TOP (solid shape): 44.56,89.84 44.59,89.92 44.67,89.94 45.96,89.79 45.82,88.68 44.56,88.7
MIC1_INN on TOP (solid shape): 45.04,90.6 45.04,89.56 45.01,89.48 44.94,89.46 43.64,89.51 43.78,90.62
MIC1_INN on BOTTOM (solid shape): 44.87,78.62 45.4,78.05 44.29,77.95 44.22,77.98 44.19,78.05 44.3,79.15
MIC1_INP on TOP (solid shape): 43.83,85 42.88,84.23 42.17,84.93 42.15,85 42.17,85.07 42.88,85.77
MIC1_INP on TOP (solid shape): 45.83,94.3 44.88,93.53 44.17,94.23 44.15,94.3 44.17,94.37 44.88,95.07
MINIPCIE_3V3 on BOTTOM: 109.19,75.13 109.27,74.95 109.45,74.88 110.31,74.88 110.49,74.95 110.57,75.13 110.57,75.97 110.49,76.15 110.31,76.22 109.45,76.22 109.27,76.15 109.19,75.97
MINIPCIE_3V3 on BOTTOM: 128.14,65.15 133.27,65.15 133.53,64.89 133.53,61.24 133.32,61.03 132.16,61.03 131.95,61.24 131.95,63.52 131.7,63.78 128.14,63.78
MINIPCIE_3V3 on ART04: 103.94,65.35 103.94,75.1 104.44,75.61 133.83,75.61 134.52,74.93 134.52,61.41 134.21,61.11 130.18,61.11 129.84,61.44 129.84,68.04 129.34,68.55 112.17,68.55 111.81,68.2 111.81,65.4 111.38,64.97 104.32,64.97
RS232_R1OUT on TOP (solid shape): 83.33,6.78 82.56,6.03 81.87,6.73 81.85,6.78 81.87,6.83 82.56,7.52
RS232_R2IN on BOTTOM (solid shape): 80.12,13.64 80.15,13.56 80.12,13.48 79.39,12.74 78.45,13.56 79.39,14.37
RS485_1_B on BOTTOM (solid shape): 54.08,13.56 53.15,12.76 52.42,13.48 52.4,13.56 52.42,13.64 53.15,14.36
SATA_5V on TOP: 125.7,24.43 125.63,24.61 125.45,24.68 124.18,24.68 124,24.61 123.93,24.43 123.93,19.78 124.08,19.63 125.45,19.63 125.7,19.88
SATA_5V on BOTTOM: 124.08,24.28 125.35,24.28 125.63,24 125.63,17.62 125.37,17.37 122.91,17.37 122.58,17.04 122.58,15.62 122.25,15.29 120.88,15.29 120.55,15.62 120.55,18.49 120.9,18.84 123.44,18.84 123.8,19.2 123.8,24
SATA_12V on TOP: 135.2,18.16 136.88,18.16 137.19,17.85 137.19,14.52 136.86,14.19 134.54,14.19 134.54,15.44 135,15.44 135.2,15.64
SATA_12V on BOTTOM: 135.05,17.75 136.78,17.75 137.03,17.5 137.03,15.08 136.8,14.86 128.35,14.86 128.02,15.19 128.02,16.94 128.24,17.17 130.33,17.17 130.78,16.71 134.85,16.71 135.05,16.91
USB_OTG_VBUS on TOP: 21.11,94.03 21.11,88.03 21.36,87.78 22.71,87.78 22.91,87.98 22.91,91.69 22.73,91.87 21.74,91.87 21.69,91.92 21.69,94.03
USB_OTG_VBUS on TOP: 26.09,90.52 26.34,90.52 26.49,90.67 26.49,94.03 25.91,94.03 25.91,90.7
USB_OTG_VBUS on BOTTOM: 21.29,89.48 22.81,89.48 22.99,89.3 22.99,88.69 23.11,88.57 24.89,88.57 25.17,88.29 25.17,86.2 25.37,86 27.28,86 27.28,85.42 24.66,85.42 24.59,85.49 24.59,87.52 24.33,87.78 21.39,87.78 21.11,88.06 21.11,89.3
USB_OTG_VBUS on BOTTOM: 21.03,90.72 21.11,90.55 21.29,90.47 26.24,90.47 26.42,90.55 26.49,90.72 26.49,91.69 26.42,91.87 26.24,91.94 21.29,91.94 21.11,91.87 21.03,91.69
N28501 on TOP: 3.2,66.87 3.2,64.94 3.1,64.84 2.36,64.84 2.29,64.92 2.29,66.87
N28533 on TOP: 5.59,67.84 3.61,67.84 3.43,67.66 3.43,64.28 3.3,64.16 2.79,64.16 2.79,62.76 5.08,62.76 5.08,64.13 4.65,64.13 4.42,64.36 4.42,67.03 4.55,67.15 5.59,67.15
N15590150 on TOP: 72.59,74.37 73.71,74.37 73.91,74.16 73.91,72.41 75.06,71.27 75.06,69.13 73.96,69.13 73.96,71.12 73.23,71.85 73.23,73.48 73.05,73.66 72.59,73.66
N15605093 on TOP: 91.77,74.37 92.91,74.37 93.12,74.16 93.12,72.31 94.23,71.19 94.23,69.13 93.14,69.13 93.14,71.12 92.41,71.85 92.41,73.48 92.23,73.66 91.77,73.66
N17345181 on TOP: 5.59,39.9 3.61,39.9 3.43,39.72 3.43,36.34 3.3,36.22 2.79,36.22 2.79,34.82 5.08,34.82 5.08,36.19 4.65,36.19 4.42,36.42 4.42,39.09 4.55,39.21 5.59,39.21
N17345235 on TOP: 3.2,38.93 3.2,37 3.1,36.9 2.36,36.9 2.29,36.98 2.29,38.93
N17366990 on TOP: 3.2,52.9 3.2,50.97 3.1,50.87 2.36,50.87 2.29,50.95 2.29,52.9
N17366996 on TOP: 5.59,53.87 3.61,53.87 3.43,53.69 3.43,50.31 3.3,50.19 2.79,50.19 2.79,48.79 5.08,48.79 5.08,50.16 4.65,50.16 4.42,50.39 4.42,53.06 4.55,53.18 5.59,53.18
